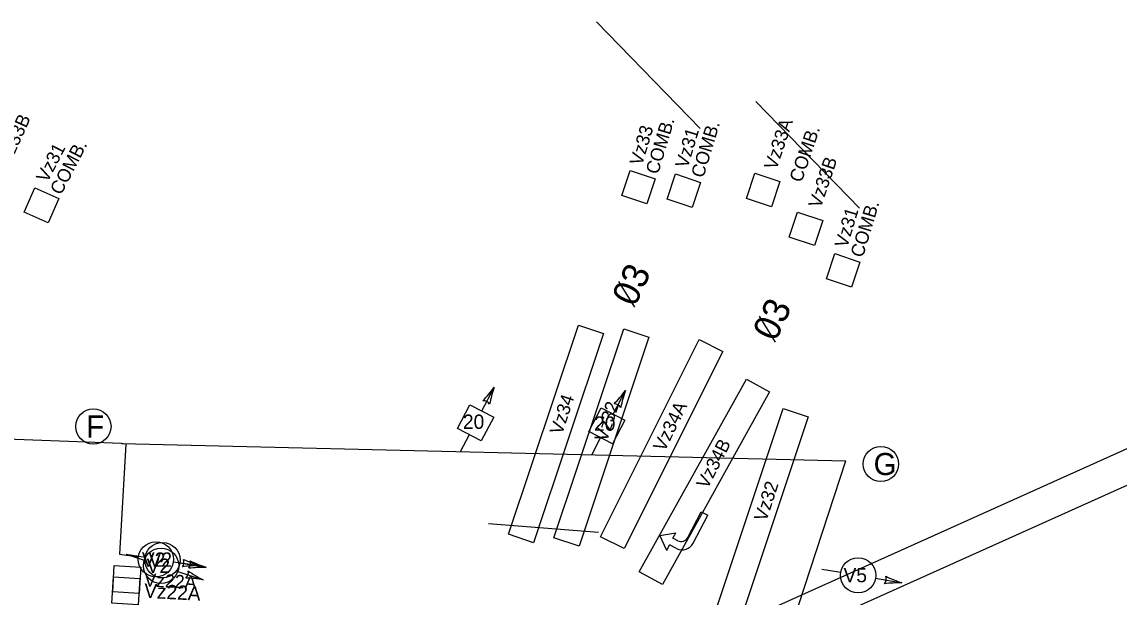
# Model space of a CAD drawing. Extents: x 647787 to 668496, y 640478 to 654412.
# Drawn here: x 661989.9 to 662238.5, y 647344.8 to 647475.3 of the extents above; entities that cross this region are included whole.
import ezdxf

# ---------------------------------------------------------------- set-up
doc = ezdxf.new("R2010")
doc.units = 0
for name, color, linetype in [('Default', 7, 'Continuous'), ('TEMP_DETECTION ZONE_Stage 2', 7, 'Continuous'), ('TEMP_DETECTION ZONE_STAGE 3', 7, 'Continuous'), ('TEMP_DETECTION_ZONE_STAGE 4', 7, 'Continuous'), ('TEMP_DETECTION_ZONE_STAGE 5', 7, 'Continuous'), ('TEMP_SIGNAL_HEAD_STAGE 2', 7, 'Continuous'), ('TEMP_SIGNAL_HEAD_Stage 3', 7, 'Continuous'), ('TEMP_SIGNAL_HEAD_STAGE4', 7, 'Continuous'), ('TEMP_SIGNAL_POLES_STAGE 1B', 7, 'Continuous'), ('TEMP_SIGNAL_POLES_STAGE 2', 7, 'Continuous'), ('TEMP_SIGNAL_POLES_STAGE 3', 7, 'Continuous'), ('TEMP_SIGNAL_POLES_STAGE 4', 7, 'Continuous'), ('TEXT_TEMP_SIGNAL_POLES_STAGE 2', 7, 'Continuous'), ('TEXT_TEMP_SIGNAL_POLES_STAGE 3', 7, 'Continuous'), ('TEXT_TEMP_SIGNAL_POLES_STAGE 4', 7, 'Continuous')]:
    doc.layers.add(name, color=color, linetype=linetype)

msp = doc.modelspace()

# ---------------------------------------------------------------- linework, layer by layer
at = {"layer": 'Default'}
for p, q in [((662125.05, 647416.44), (662128.68, 647410.56)), ((662156.96, 647408.56), (662160.58, 647402.68)), ((662140.76, 647358.36), (662143.78, 647364.21)), ((662142, 647357.08), (662145.28, 647363.44)), ((662143.78, 647364.21), (662145.28, 647363.44)), ((662134.42, 647358.78), (662138.05, 647359.44)), ((662135.99, 647355.44), (662134.42, 647358.78)), ((662137.41, 647358.19), (662138.05, 647359.44)), ((662138.49, 647357.63), (662137.41, 647358.19)), ((662135.99, 647355.44), (662136.63, 647356.69)), ((662138.22, 647355.87), (662136.63, 647356.69))]:
    msp.add_line(p, q, dxfattribs=at)
for points in [[(662120.07, 647475.29), (662143.58, 647451.1)], [(662120.07, 647475.29), (662143.58, 647451.1)], [(662120.07, 647475.29), (662143.58, 647451.1)], [(662156.2, 647457.21), (662179.71, 647433.02)], [(662536.7, 647412.12), (662361.86, 647433.21), (662136.44, 647331.77)], [(662508.55, 647391.12), (662333.71, 647412.21), (662108.29, 647310.77)], [(662508.55, 647391.12), (662333.71, 647412.21), (662108.29, 647310.77)], [(662508.55, 647391.12), (662333.71, 647412.21), (662108.29, 647310.77)]]:
    msp.add_lwpolyline(points, dxfattribs=at)
for centre, radius in [((662139.26, 647359.13), 1.69), ((662139.51, 647358.37), 2.81)]:
    msp.add_arc(centre, radius, 242.7089, 332.7089, dxfattribs=at)
at = {"layer": 'TEMP_DETECTION ZONE_Stage 2'}
msp.add_lwpolyline([(661995.84, 647429.74), (661990.36, 647432.17), (661992.78, 647437.66), (661998.27, 647435.23)], close=True, dxfattribs=at)
at = {"layer": 'TEMP_DETECTION ZONE_STAGE 3'}
for points in [[(662159.73, 647433.37), (662154.04, 647435.27), (662155.94, 647440.96), (662161.63, 647439.06)], [(662169.45, 647424.58), (662163.76, 647426.48), (662165.66, 647432.17), (662171.35, 647430.27)], [(662177.89, 647415.14), (662172.2, 647417.04), (662174.1, 647422.73), (662179.79, 647420.83)], [(662126.36, 647355.83), (662120.99, 647358.51), (662143.35, 647403.23), (662148.72, 647400.55)], [(662135.01, 647347.66), (662129.76, 647350.58), (662154.06, 647394.28), (662159.3, 647391.36)], [(662152.25, 647338.3), (662146.56, 647340.2), (662162.39, 647387.63), (662168.08, 647385.73)]]:
    msp.add_lwpolyline(points, close=True, dxfattribs=at)
at = {"layer": 'TEMP_DETECTION_ZONE_STAGE 4'}
for points in [[(662131.48, 647434.01), (662125.79, 647435.91), (662127.69, 647441.6), (662133.38, 647439.7)], [(662141.76, 647433.21), (662136.07, 647435.11), (662137.97, 647440.8), (662143.66, 647438.9)], [(662105.84, 647357.18), (662100.15, 647359.08), (662115.98, 647406.5), (662121.67, 647404.61)], [(662116.12, 647356.38), (662110.43, 647358.28), (662126.25, 647405.71), (662131.94, 647403.81)]]:
    msp.add_lwpolyline(points, close=True, dxfattribs=at)
at = {"layer": 'TEMP_DETECTION_ZONE_STAGE 5'}
msp.add_lwpolyline([(662016.43, 647345.67), (662010.44, 647346.03), (662010.81, 647352.02), (662016.79, 647351.66)], close=True, dxfattribs=at)
at = {"layer": 'TEMP_SIGNAL_HEAD_STAGE 2'}
for p, q in [((662011.98, 647354.58), (662016.27, 647353.97)), ((662024.19, 647352.85), (662030.2, 647352))]:
    msp.add_line(p, q, dxfattribs=at)
msp.add_lwpolyline([(662013.44, 647379.53), (662011.98, 647354.58)], dxfattribs=at)
msp.add_circle((662020.23, 647353.41), 4, dxfattribs=at)
for centre, radius, start, end in [((662024.98, 647352.74), 1.63, 320.1047, 23.7993), ((662038.64, 647380.24), 29.47, 245.6156, 253.3537), ((662030.49, 647322.53), 29.47, 90.5713, 98.3094)]:
    msp.add_arc(centre, radius, start, end, dxfattribs=at)
at = {"layer": 'TEMP_SIGNAL_HEAD_Stage 3'}
for p, q in [((662123.83, 647386.35), (662126.63, 647391.7)), ((662119.01, 647377.12), (662121.02, 647380.98)), ((662013.5, 647354.58), (662017.77, 647353.87)), ((662025.67, 647352.58), (662031.65, 647351.59)), ((662171.16, 647351.2), (662175.43, 647350.46)), ((662183.31, 647349.1), (662189.29, 647348.06))]:
    msp.add_line(p, q, dxfattribs=at)
msp.add_lwpolyline([(662123.71, 647379.57), (662118.33, 647382.38), (662121.14, 647387.75), (662126.52, 647384.94)], close=True, dxfattribs=at)
for centre in [(662021.72, 647353.23), (662179.37, 647349.78)]:
    msp.add_circle(centre, 4, dxfattribs=at)
for centre, radius, start, end in [((662102.85, 647409.11), 29.47, 316.0491, 323.7872), ((662154.5, 647382.11), 29.47, 161.0039, 168.742), ((662124.19, 647387.03), 1.63, 30.5482, 94.2429), ((662026.46, 647352.45), 1.63, 318.8159, 22.5105), ((662040.73, 647379.63), 29.47, 244.3269, 252.065), ((662031.28, 647322.12), 29.47, 89.2825, 97.0206), ((662184.1, 647348.96), 1.63, 318.3142, 22.0088), ((662188.66, 647318.59), 29.47, 88.7808, 96.5189), ((662198.61, 647376.02), 29.47, 243.8251, 251.5633)]:
    msp.add_arc(centre, radius, start, end, dxfattribs=at)
at = {"layer": 'TEMP_SIGNAL_HEAD_STAGE4'}
for p, q in [((662094.1, 647387.06), (662096.9, 647392.41)), ((662089.28, 647377.84), (662091.29, 647381.69)), ((662120.56, 647359.5), (662095.64, 647361.43)), ((662013.5, 647354.58), (662017.61, 647353.21)), ((662025.2, 647350.68), (662030.95, 647348.76))]:
    msp.add_line(p, q, dxfattribs=at)
msp.add_lwpolyline([(662093.98, 647380.28), (662088.6, 647383.09), (662091.41, 647388.47), (662096.79, 647385.66)], close=True, dxfattribs=at)
msp.add_circle((662021.4, 647351.94), 4, dxfattribs=at)
for centre, radius, start, end in [((662073.12, 647409.83), 29.47, 316.0491, 323.7872), ((662124.77, 647382.82), 29.47, 161.0039, 168.742), ((662094.46, 647387.75), 1.63, 30.5482, 94.2429), ((662025.96, 647350.42), 1.63, 309.7122, 13.4069), ((662044.35, 647375.01), 29.47, 235.2232, 242.9613), ((662025.92, 647319.72), 29.47, 80.1789, 87.917)]:
    msp.add_arc(centre, radius, start, end, dxfattribs=at)
at = {"layer": 'TEMP_SIGNAL_POLES_STAGE 1B'}
msp.add_lwpolyline([(662016.25, 647343.08), (662010.26, 647343.44), (662010.62, 647349.43), (662016.61, 647349.06)], close=True, dxfattribs=at)
at = {"layer": 'TEMP_SIGNAL_POLES_STAGE 2'}
for p, q in [((662012.45, 647379.68), (661894.7, 647383.95)), ((662013.44, 647379.53), (662012.45, 647379.68))]:
    msp.add_line(p, q, dxfattribs=at)
at = {"layer": 'TEMP_SIGNAL_POLES_STAGE 3'}
for p, q in [((662012.45, 647379.68), (662176.55, 647375.74)), ((662129.5, 647231.69), (662176.55, 647375.75))]:
    msp.add_line(p, q, dxfattribs=at)
at = {"layer": 'TEMP_SIGNAL_POLES_STAGE 4'}
for p, q in [((662012.45, 647379.68), (662176.55, 647375.74)), ((662129.5, 647231.69), (662176.55, 647375.75))]:
    msp.add_line(p, q, dxfattribs=at)
at = {"layer": 'TEXT_TEMP_SIGNAL_POLES_STAGE 2'}
msp.add_circle((662006.06, 647383.53), 4, dxfattribs=at)
at = {"layer": 'TEXT_TEMP_SIGNAL_POLES_STAGE 3'}
for centre in [(662006.06, 647383.53), (662184.52, 647375.02)]:
    msp.add_circle(centre, 4, dxfattribs=at)
at = {"layer": 'TEXT_TEMP_SIGNAL_POLES_STAGE 4'}
for centre in [(662006.06, 647383.53), (662184.52, 647375.02)]:
    msp.add_circle(centre, 4, dxfattribs=at)

# ---------------------------------------------------------------- texts
at = {"layer": 'Default'}
for p in [(662128.79, 647410.46), (662160.69, 647402.58)]:
    msp.add_text('03', height=6, rotation=65.2141, dxfattribs=at).set_placement(p)
at = {"layer": 'TEMP_DETECTION ZONE_Stage 2'}
for s, rotation, p in [('Vz33B', 65.6969, (661987.06, 647442.72)), ('COMB.', 62.6086, (661998.74, 647435.86)), ('Vz31', 62.6086, (661995.62, 647438.66))]:
    msp.add_text(s, height=3, rotation=rotation, dxfattribs=at).set_placement(p)
at = {"layer": 'TEMP_DETECTION ZONE_STAGE 3'}
for s, rotation, p in [('Vz33A', 71.1265, (662160.8, 647441.54)), ('COMB.', 71.1265, (662166.54, 647438.7)), ('Vz33B', 71.1265, (662170.86, 647432.87)), ('Vz31', 73.212, (662176.85, 647423.86)), ('COMB.', 73.212, (662180.43, 647421.68)), ('Vz34A', 63.8134, (662135.48, 647377.64)), ('Vz34B', 62.8693, (662145.21, 647369.18)), ('Vz32', 71.9587, (662158.55, 647361.81))]:
    msp.add_text(s, height=3, rotation=rotation, dxfattribs=at).set_placement(p)
at = {"layer": 'TEMP_DETECTION_ZONE_STAGE 4'}
for s, rotation, p in [('COMB.', 73.212, (662134.02, 647440.55)), ('Vz33', 73.212, (662130.37, 647442.52)), ('Vz31', 73.212, (662140.71, 647441.93)), ('COMB.', 73.212, (662144.3, 647439.75)), ('Vz34', 71.9202, (662112.26, 647381.49)), ('Vz32', 71.9587, (662122.41, 647379.89))]:
    msp.add_text(s, height=3, rotation=rotation, dxfattribs=at).set_placement(p)
at = {"layer": 'TEMP_DETECTION_ZONE_STAGE 5'}
msp.add_text('Vz22A', height=3, rotation=356.9362, dxfattribs=at).set_placement((662017.54, 647347.29))
at = {"layer": 'TEMP_SIGNAL_POLES_STAGE 1B'}
msp.add_text('Vz22A', height=3.25, rotation=356.9362, dxfattribs=at).set_placement((662017.5, 647344.69))
at = {"layer": 'TEXT_TEMP_SIGNAL_POLES_STAGE 2'}
for s, height, p in [('F', 5, (662004.42, 647381.03)), ('V2', 3.25, (662017.06, 647351.72))]:
    msp.add_text(s, height=height, dxfattribs=at).set_placement(p)
at = {"layer": 'TEXT_TEMP_SIGNAL_POLES_STAGE 3'}
for s, height, p in [('F', 5, (662004.42, 647381.03)), ('20', 3.25, (662119.52, 647382.57)), ('G', 5, (662182.88, 647372.52)), ('V2', 3.25, (662018.57, 647351.72)), ('V5', 3.25, (662176.06, 647348.2))]:
    msp.add_text(s, height=height, dxfattribs=at).set_placement(p)
at = {"layer": 'TEXT_TEMP_SIGNAL_POLES_STAGE 4'}
for s, height, p in [('F', 5, (662004.42, 647381.03)), ('20', 3.25, (662089.81, 647382.99)), ('G', 5, (662182.88, 647372.52)), ('V2', 3.25, (662018.13, 647350.31))]:
    msp.add_text(s, height=height, dxfattribs=at).set_placement(p)

doc.saveas('drawing.dxf')
